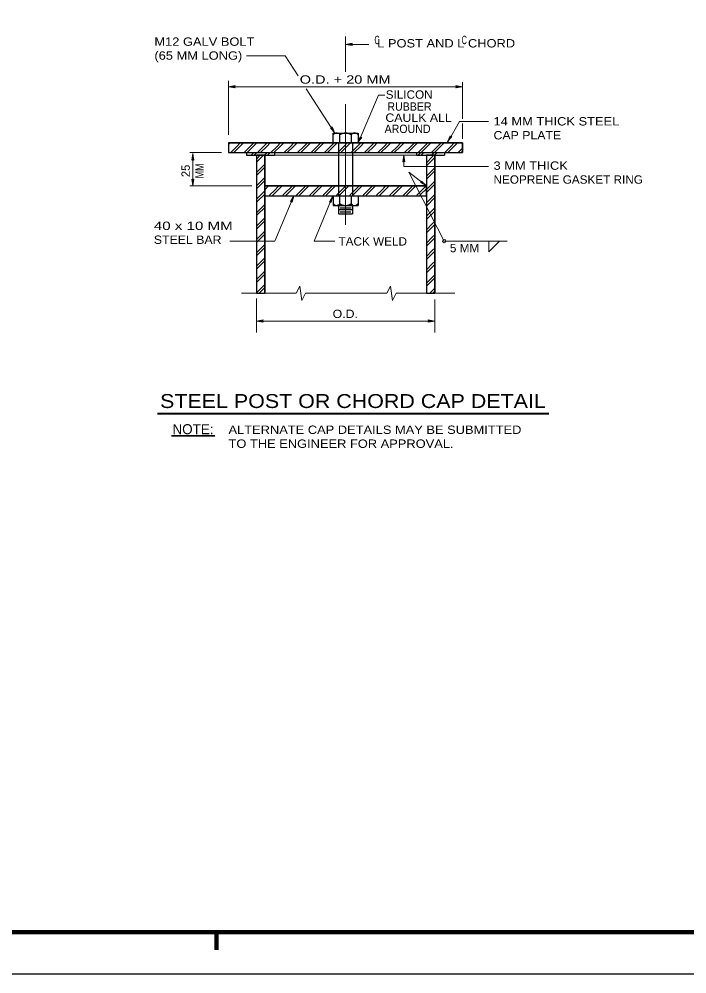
# Model space of a CAD drawing. Extents: x 312601.859 to 312602.7, y 144420.109 to 144420.704.
# Drawn here: x 312602.209 to 312602.4486, y 144420.1095 to 144420.4522 of the extents above; entities that cross this region are included whole.
import ezdxf
from ezdxf.enums import TextEntityAlignment as Align

# ---------------------------------------------------------------- set-up
doc = ezdxf.new("R2010")
doc.units = 0
doc.header["$LTSCALE"] = 0.0012
doc.linetypes.add('DOT_DASHED', pattern=[7.7, 5, -1.2, 0.3, -1.2])
doc.linetypes.add('MEDIUM_DASHED', pattern=[4.5, 3, -1.5])
for name, color, linetype, lineweight in [('1', 7, 'Continuous', 13), ('2', 7, 'Continuous', 13), ('39', 7, 'Continuous', 13)]:
    doc.layers.add(name, color=color, linetype=linetype, lineweight=lineweight)

msp = doc.modelspace()

# ---------------------------------------------------------------- hatches: boundary and pattern name
at = {"layer": '39'}
for points in [[(312602.3283, 144420.4431), (312602.3285, 144420.4427), (312602.3261, 144420.4431), (312602.3285, 144420.4435)], [(312602.2863, 144420.4279), (312602.2865, 144420.4275), (312602.2841, 144420.4279), (312602.2865, 144420.4283)], [(312602.3659, 144420.4279), (312602.3657, 144420.4283), (312602.3681, 144420.4279), (312602.3657, 144420.4275)], [(312602.3211, 144420.4131), (312602.3213, 144420.4135), (312602.3223, 144420.4113), (312602.3207, 144420.4131)], [(312602.3315, 144420.4097), (312602.3319, 144420.4097), (312602.3304, 144420.4078), (312602.3313, 144420.4099)], [(312602.3638, 144420.41), (312602.3642, 144420.41), (312602.3627, 144420.4081), (312602.3636, 144420.4103)], [(312602.2713, 144420.4018), (312602.2709, 144420.4016), (312602.2713, 144420.404), (312602.2717, 144420.4016)], [(312602.347, 144420.4011), (312602.3466, 144420.4009), (312602.347, 144420.4033), (312602.3474, 144420.4009)], [(312602.2713, 144420.3945), (312602.2717, 144420.3947), (312602.2713, 144420.3923), (312602.2709, 144420.3947)], [(312602.3534, 144420.3936), (312602.3534, 144420.394), (312602.3551, 144420.3923), (312602.353, 144420.3935)], [(312602.3067, 144420.3868), (312602.3063, 144420.3867), (312602.3075, 144420.3888), (312602.3069, 144420.3865)], [(312602.3207, 144420.3867), (312602.3203, 144420.3866), (312602.3215, 144420.3887), (312602.3209, 144420.3864)], [(312602.2963, 144420.3438), (312602.2965, 144420.3434), (312602.2941, 144420.3438), (312602.2965, 144420.3442)], [(312602.3559, 144420.3438), (312602.3557, 144420.3442), (312602.3581, 144420.3438), (312602.3557, 144420.3434)]]:
    msp.add_hatch(color=256, dxfattribs=at).paths.add_polyline_path(points)

# ---------------------------------------------------------------- linework, layer by layer
at = {"layer": '1', "lineweight": 40}
msp.add_line((312602.2586, 144420.3106), (312602.399, 144420.3106), dxfattribs=at)
at = {"layer": '2'}
for p, q in [((312602.3261, 144420.4459), (312602.3261, 144420.4332)), ((312602.3261, 144420.4431), (312602.3344, 144420.4431)), ((312602.2906, 144420.439), (312602.3044, 144420.439)), ((312602.3091, 144420.4318), (312602.3044, 144420.439)), ((312602.2841, 144420.43), (312602.2841, 144420.4107)), ((312602.3681, 144420.4296), (312602.3681, 144420.4164)), ((312602.2841, 144420.4279), (312602.3681, 144420.4279)), ((312602.3223, 144420.4113), (312602.312, 144420.4272)), ((312602.3628, 144420.408), (312602.367, 144420.4154)), ((312602.367, 144420.4154), (312602.3774, 144420.4154)), ((312602.3681, 144420.4147), (312602.3681, 144420.4092)), ((312602.3216, 144420.4107), (312602.3216, 144420.4113)), ((312602.2841, 144420.4072), (312602.2847, 144420.4078)), ((312602.2849, 144420.4043), (312602.2871, 144420.4065)), ((312602.286, 144420.4043), (312602.2882, 144420.4065)), ((312602.2871, 144420.4065), (312602.2882, 144420.4076)), ((312602.2882, 144420.4065), (312602.2895, 144420.4078)), ((312602.2882, 144420.4076), (312602.2884, 144420.4078)), ((312602.2897, 144420.4043), (312602.2919, 144420.4065)), ((312602.2908, 144420.4043), (312602.293, 144420.4065)), ((312602.2919, 144420.4065), (312602.2932, 144420.4078)), ((312602.293, 144420.4065), (312602.2943, 144420.4078)), ((312602.2945, 144420.4043), (312602.2967, 144420.4065)), ((312602.2956, 144420.4043), (312602.2978, 144420.4065)), ((312602.2967, 144420.4065), (312602.298, 144420.4078)), ((312602.2978, 144420.4065), (312602.2991, 144420.4078)), ((312602.2993, 144420.4043), (312602.3015, 144420.4065)), ((312602.3004, 144420.4043), (312602.3026, 144420.4065)), ((312602.3015, 144420.4065), (312602.3028, 144420.4078)), ((312602.3026, 144420.4065), (312602.3039, 144420.4078)), ((312602.3041, 144420.4043), (312602.3063, 144420.4065)), ((312602.3052, 144420.4043), (312602.3074, 144420.4065)), ((312602.3063, 144420.4065), (312602.3074, 144420.4076)), ((312602.3074, 144420.4065), (312602.3087, 144420.4078)), ((312602.3074, 144420.4076), (312602.3076, 144420.4078)), ((312602.3089, 144420.4043), (312602.3111, 144420.4065)), ((312602.31, 144420.4043), (312602.3122, 144420.4065)), ((312602.3111, 144420.4065), (312602.3124, 144420.4078)), ((312602.3122, 144420.4065), (312602.3135, 144420.4078)), ((312602.3137, 144420.4043), (312602.3159, 144420.4065)), ((312602.3148, 144420.4043), (312602.317, 144420.4065)), ((312602.3159, 144420.4065), (312602.3172, 144420.4078)), ((312602.317, 144420.4065), (312602.3183, 144420.4078)), ((312602.3185, 144420.4043), (312602.3207, 144420.4065)), ((312602.3196, 144420.4043), (312602.3218, 144420.4065)), ((312602.3207, 144420.4065), (312602.322, 144420.4078)), ((312602.3218, 144420.4065), (312602.3231, 144420.4078)), ((312602.3233, 144420.4043), (312602.3255, 144420.4065)), ((312602.3244, 144420.4043), (312602.3266, 144420.4065)), ((312602.3255, 144420.4065), (312602.3266, 144420.4076)), ((312602.3266, 144420.4065), (312602.3279, 144420.4078)), ((312602.3266, 144420.4076), (312602.3268, 144420.4078)), ((312602.3281, 144420.4043), (312602.3303, 144420.4065)), ((312602.3292, 144420.4043), (312602.3314, 144420.4065)), ((312602.3303, 144420.4065), (312602.3316, 144420.4078)), ((312602.3314, 144420.4065), (312602.3327, 144420.4078)), ((312602.3329, 144420.4043), (312602.3351, 144420.4065)), ((312602.334, 144420.4043), (312602.3362, 144420.4065)), ((312602.3351, 144420.4065), (312602.3364, 144420.4078)), ((312602.3362, 144420.4065), (312602.3375, 144420.4078)), ((312602.3377, 144420.4043), (312602.3399, 144420.4065)), ((312602.3388, 144420.4043), (312602.341, 144420.4065)), ((312602.3399, 144420.4065), (312602.3412, 144420.4078)), ((312602.341, 144420.4065), (312602.3423, 144420.4078)), ((312602.3425, 144420.4043), (312602.3447, 144420.4065)), ((312602.3436, 144420.4043), (312602.3458, 144420.4065)), ((312602.3447, 144420.4065), (312602.3458, 144420.4076)), ((312602.3458, 144420.4065), (312602.3471, 144420.4078)), ((312602.3458, 144420.4076), (312602.346, 144420.4078)), ((312602.3473, 144420.4043), (312602.3495, 144420.4065)), ((312602.3484, 144420.4043), (312602.3506, 144420.4065)), ((312602.3495, 144420.4065), (312602.3508, 144420.4078)), ((312602.3506, 144420.4065), (312602.3519, 144420.4078)), ((312602.3521, 144420.4043), (312602.3543, 144420.4065)), ((312602.3532, 144420.4043), (312602.3554, 144420.4065)), ((312602.3543, 144420.4065), (312602.3556, 144420.4078)), ((312602.3554, 144420.4065), (312602.3567, 144420.4078)), ((312602.3569, 144420.4043), (312602.3591, 144420.4065)), ((312602.358, 144420.4043), (312602.3602, 144420.4065)), ((312602.3591, 144420.4065), (312602.3604, 144420.4078)), ((312602.3602, 144420.4065), (312602.3615, 144420.4078)), ((312602.3617, 144420.4043), (312602.3639, 144420.4065)), ((312602.3628, 144420.4043), (312602.365, 144420.4065)), ((312602.3639, 144420.4065), (312602.365, 144420.4076)), ((312602.365, 144420.4065), (312602.3663, 144420.4078)), ((312602.365, 144420.4076), (312602.3652, 144420.4078)), ((312602.3665, 144420.4043), (312602.3681, 144420.4059)), ((312602.3676, 144420.4043), (312602.3681, 144420.4048)), ((312602.2702, 144420.4043), (312602.2816, 144420.4043)), ((312602.2713, 144420.404), (312602.2713, 144420.3923)), ((312602.2922, 144420.4033), (312602.2932, 144420.4043)), ((312602.2933, 144420.4033), (312602.2943, 144420.4043)), ((312602.2941, 144420.4019), (312602.2955, 144420.4033)), ((312602.2941, 144420.4008), (312602.2945, 144420.4012)), ((312602.2945, 144420.4012), (312602.2966, 144420.4033)), ((312602.297, 144420.4033), (312602.298, 144420.4043)), ((312602.2981, 144420.4033), (312602.2991, 144420.4043)), ((312602.3006, 144420.4033), (312602.3516, 144420.4033)), ((312602.347, 144420.3993), (312602.347, 144420.4033)), ((312602.3532, 144420.4033), (312602.3536, 144420.4037)), ((312602.3536, 144420.4037), (312602.3542, 144420.4043)), ((312602.3551, 144420.4006), (312602.3572, 144420.4027)), ((312602.3551, 144420.3995), (312602.3581, 144420.4025)), ((312602.3569, 144420.4033), (312602.3573, 144420.4037)), ((312602.3572, 144420.4027), (312602.3578, 144420.4033)), ((312602.3573, 144420.4037), (312602.3579, 144420.4043)), ((312602.358, 144420.4033), (312602.3584, 144420.4037)), ((312602.3584, 144420.4037), (312602.359, 144420.4043)), ((312602.2941, 144420.3971), (312602.2971, 144420.4001)), ((312602.2945, 144420.3964), (312602.2971, 144420.399)), ((312602.347, 144420.3993), (312602.3774, 144420.3993)), ((312602.3551, 144420.3958), (312602.3572, 144420.3979)), ((312602.3551, 144420.3947), (312602.3581, 144420.3977)), ((312602.3572, 144420.3979), (312602.3581, 144420.3988)), ((312602.2941, 144420.396), (312602.2945, 144420.3964)), ((312602.2941, 144420.3923), (312602.2971, 144420.3953)), ((312602.2945, 144420.3916), (312602.2971, 144420.3942)), ((312602.2702, 144420.3923), (312602.2925, 144420.3923)), ((312602.2941, 144420.3912), (312602.2945, 144420.3916)), ((312602.2971, 144420.3909), (312602.2985, 144420.3923)), ((312602.2971, 144420.392), (312602.2974, 144420.3923)), ((312602.3003, 144420.3893), (312602.3033, 144420.3923)), ((312602.3003, 144420.3904), (312602.3022, 144420.3923)), ((312602.304, 144420.3893), (312602.307, 144420.3923)), ((312602.3051, 144420.3893), (312602.3081, 144420.3923)), ((312602.3088, 144420.3893), (312602.3118, 144420.3923)), ((312602.3099, 144420.3893), (312602.3129, 144420.3923)), ((312602.3136, 144420.3893), (312602.3166, 144420.3923)), ((312602.3147, 144420.3893), (312602.3177, 144420.3923)), ((312602.3195, 144420.3893), (312602.3225, 144420.3923)), ((312602.3195, 144420.3904), (312602.3214, 144420.3923)), ((312602.3232, 144420.3893), (312602.3262, 144420.3923)), ((312602.3243, 144420.3893), (312602.3273, 144420.3923)), ((312602.328, 144420.3893), (312602.331, 144420.3923)), ((312602.3291, 144420.3893), (312602.3321, 144420.3923)), ((312602.3328, 144420.3893), (312602.3358, 144420.3923)), ((312602.3339, 144420.3893), (312602.3369, 144420.3923)), ((312602.3387, 144420.3893), (312602.3417, 144420.3923)), ((312602.3387, 144420.3904), (312602.3406, 144420.3923)), ((312602.3424, 144420.3893), (312602.3454, 144420.3923)), ((312602.3435, 144420.3893), (312602.3465, 144420.3923)), ((312602.3472, 144420.3893), (312602.3502, 144420.3923)), ((312602.3483, 144420.3893), (312602.3513, 144420.3923)), ((312602.3551, 144420.3923), (312602.3487, 144420.3923)), ((312602.352, 144420.3893), (312602.355, 144420.3923)), ((312602.3531, 144420.3893), (312602.3551, 144420.3913)), ((312602.3551, 144420.391), (312602.3572, 144420.3931)), ((312602.3551, 144420.3899), (312602.3581, 144420.3929)), ((312602.3572, 144420.3931), (312602.3581, 144420.394)), ((312602.2941, 144420.3875), (312602.2971, 144420.3905)), ((312602.2945, 144420.3868), (312602.2971, 144420.3894)), ((312602.2987, 144420.3888), (312602.2992, 144420.3893)), ((312602.2992, 144420.3893), (312602.3003, 144420.3904)), ((312602.2998, 144420.3888), (312602.3003, 144420.3893)), ((312602.3035, 144420.3888), (312602.304, 144420.3893)), ((312602.3046, 144420.3888), (312602.3051, 144420.3893)), ((312602.3083, 144420.3888), (312602.3088, 144420.3893)), ((312602.3094, 144420.3888), (312602.3099, 144420.3893)), ((312602.3131, 144420.3888), (312602.3136, 144420.3893)), ((312602.3142, 144420.3888), (312602.3147, 144420.3893)), ((312602.3215, 144420.3887), (312602.3148, 144420.3725)), ((312602.3179, 144420.3888), (312602.3184, 144420.3893)), ((312602.3184, 144420.3893), (312602.3195, 144420.3904)), ((312602.319, 144420.3888), (312602.3195, 144420.3893)), ((312602.3227, 144420.3888), (312602.3232, 144420.3893)), ((312602.3238, 144420.3888), (312602.3243, 144420.3893)), ((312602.3275, 144420.3888), (312602.328, 144420.3893)), ((312602.3286, 144420.3888), (312602.3291, 144420.3893)), ((312602.3323, 144420.3888), (312602.3328, 144420.3893)), ((312602.3334, 144420.3888), (312602.3339, 144420.3893)), ((312602.3371, 144420.3888), (312602.3376, 144420.3893)), ((312602.3376, 144420.3893), (312602.3387, 144420.3904)), ((312602.3382, 144420.3888), (312602.3387, 144420.3893)), ((312602.3419, 144420.3888), (312602.3424, 144420.3893)), ((312602.343, 144420.3888), (312602.3435, 144420.3893)), ((312602.3467, 144420.3888), (312602.3472, 144420.3893)), ((312602.3478, 144420.3888), (312602.3483, 144420.3893)), ((312602.3515, 144420.3888), (312602.352, 144420.3893)), ((312602.3526, 144420.3888), (312602.3531, 144420.3893)), ((312602.3551, 144420.3862), (312602.3572, 144420.3883)), ((312602.3551, 144420.3851), (312602.3581, 144420.3881)), ((312602.3572, 144420.3883), (312602.3581, 144420.3892)), ((312602.2941, 144420.3864), (312602.2945, 144420.3868)), ((312602.2941, 144420.3827), (312602.2971, 144420.3857)), ((312602.2945, 144420.382), (312602.2971, 144420.3846)), ((312602.3572, 144420.3835), (312602.3581, 144420.3844)), ((312602.2941, 144420.3816), (312602.2945, 144420.382)), ((312602.2941, 144420.3779), (312602.2971, 144420.3809)), ((312602.3551, 144420.3814), (312602.3572, 144420.3835)), ((312602.3551, 144420.3803), (312602.3581, 144420.3833)), ((312602.2941, 144420.3768), (312602.2945, 144420.3772)), ((312602.2945, 144420.3772), (312602.2971, 144420.3798)), ((312602.3551, 144420.3766), (312602.3572, 144420.3787)), ((312602.3551, 144420.3755), (312602.3581, 144420.3785)), ((312602.3572, 144420.3787), (312602.3581, 144420.3796)), ((312602.2941, 144420.3731), (312602.2971, 144420.3761)), ((312602.2945, 144420.3724), (312602.2971, 144420.375)), ((312602.3551, 144420.3718), (312602.3572, 144420.3739)), ((312602.3551, 144420.3707), (312602.3581, 144420.3737)), ((312602.3572, 144420.3739), (312602.3581, 144420.3748)), ((312602.2941, 144420.372), (312602.2945, 144420.3724)), ((312602.2941, 144420.3683), (312602.2971, 144420.3713)), ((312602.2945, 144420.3676), (312602.2971, 144420.3702)), ((312602.3223, 144420.3725), (312602.3148, 144420.3725)), ((312602.3841, 144420.3725), (312602.3615, 144420.3725)), ((312602.2941, 144420.3672), (312602.2945, 144420.3676)), ((312602.3551, 144420.367), (312602.3572, 144420.3691)), ((312602.3551, 144420.3659), (312602.3581, 144420.3689)), ((312602.3572, 144420.3691), (312602.3581, 144420.37)), ((312602.2941, 144420.3635), (312602.2971, 144420.3665)), ((312602.2945, 144420.3628), (312602.2971, 144420.3654)), ((312602.3551, 144420.3622), (312602.3572, 144420.3643)), ((312602.3551, 144420.3611), (312602.3581, 144420.3641)), ((312602.3572, 144420.3643), (312602.3581, 144420.3652)), ((312602.2941, 144420.3624), (312602.2945, 144420.3628)), ((312602.2941, 144420.3587), (312602.2971, 144420.3617)), ((312602.2945, 144420.358), (312602.2971, 144420.3606)), ((312602.3572, 144420.3595), (312602.3581, 144420.3604)), ((312602.2941, 144420.3576), (312602.2945, 144420.358)), ((312602.2941, 144420.3539), (312602.2971, 144420.3569)), ((312602.3551, 144420.3574), (312602.3572, 144420.3595)), ((312602.3551, 144420.3563), (312602.3581, 144420.3593)), ((312602.2887, 144420.3538), (312602.3084, 144420.3538)), ((312602.2951, 144420.3538), (312602.2971, 144420.3558)), ((312602.3117, 144420.3538), (312602.3409, 144420.3538)), ((312602.3442, 144420.3538), (312602.3653, 144420.3538)), ((312602.3563, 144420.3538), (312602.3572, 144420.3547)), ((312602.3572, 144420.3547), (312602.3581, 144420.3556)), ((312602.3574, 144420.3538), (312602.3581, 144420.3545)), ((312602.2941, 144420.3519), (312602.2941, 144420.3397)), ((312602.3581, 144420.3515), (312602.3581, 144420.3397)), ((312602.2941, 144420.3438), (312602.3581, 144420.3438))]:
    msp.add_line(p, q, dxfattribs=at)
at = {"layer": '2', "linetype": 'DOT_DASHED'}
msp.add_line((312602.3261, 144420.4217), (312602.3261, 144420.3784), dxfattribs=at)
at = {"layer": '2', "lineweight": 25}
for p, q in [((312602.3241, 144420.4078), (312602.3241, 144420.4113)), ((312602.3281, 144420.4113), (312602.3281, 144420.4078)), ((312602.3306, 144420.4113), (312602.3306, 144420.4078)), ((312602.2841, 144420.4078), (312602.3681, 144420.4078)), ((312602.2841, 144420.4078), (312602.2841, 144420.4043)), ((312602.3681, 144420.4078), (312602.3681, 144420.4043)), ((312602.2841, 144420.4043), (312602.3681, 144420.4043)), ((312602.2841, 144420.4043), (312602.3132, 144420.4043)), ((312602.2906, 144420.4043), (312602.2906, 144420.4033)), ((312602.2906, 144420.4033), (312602.3006, 144420.4033)), ((312602.2941, 144420.4033), (312602.2941, 144420.3538)), ((312602.2971, 144420.4033), (312602.2971, 144420.3538)), ((312602.3006, 144420.4043), (312602.3006, 144420.4033)), ((312602.3236, 144420.4043), (312602.3236, 144420.3923)), ((312602.3286, 144420.4043), (312602.3286, 144420.3923)), ((312602.3516, 144420.4043), (312602.3516, 144420.4033)), ((312602.3516, 144420.4033), (312602.3616, 144420.4033)), ((312602.3551, 144420.4033), (312602.3551, 144420.3538)), ((312602.3581, 144420.4033), (312602.3581, 144420.3538)), ((312602.3616, 144420.4043), (312602.3616, 144420.4033)), ((312602.2971, 144420.3923), (312602.3551, 144420.3923)), ((312602.2971, 144420.3888), (312602.3551, 144420.3888)), ((312602.3241, 144420.3853), (312602.3241, 144420.3888)), ((312602.3281, 144420.3888), (312602.3281, 144420.3853)), ((312602.3306, 144420.3888), (312602.3306, 144420.3853)), ((312602.3236, 144420.3853), (312602.3236, 144420.3823)), ((312602.3242, 144420.3845), (312602.3281, 144420.3845)), ((312602.3286, 144420.3853), (312602.3286, 144420.3823)), ((312602.3236, 144420.3838), (312602.3286, 144420.3838)), ((312602.3236, 144420.3823), (312602.3286, 144420.3823)), ((312602.3242, 144420.383), (312602.328, 144420.383))]:
    msp.add_line(p, q, dxfattribs=at)
at = {"layer": '2', "linetype": 'MEDIUM_DASHED', "lineweight": 25}
for p, q in [((312602.3236, 144420.4078), (312602.3236, 144420.4043)), ((312602.3286, 144420.4078), (312602.3286, 144420.4043)), ((312602.3236, 144420.3923), (312602.3236, 144420.3888)), ((312602.3286, 144420.3923), (312602.3286, 144420.3888))]:
    msp.add_line(p, q, dxfattribs=at)
at = {"layer": '2', "lineweight": 35}
msp.add_line((312602.2792, 144420.3026), (312602.2636, 144420.3026), dxfattribs=at)
at = {"layer": '2'}
for points in [[(312602.3306, 144420.4078), (312602.3379, 144420.4249), (312602.3402, 144420.4249)], [(312602.3521, 144420.4033), (312602.3525, 144420.4037), (312602.3531, 144420.4043)], [(312602.3551, 144420.3923), (312602.3488, 144420.3972), (312602.3615, 144420.3725)], [(312602.3075, 144420.3888), (312602.3007, 144420.3725), (312602.2846, 144420.3725)], [(312602.3775, 144420.3725), (312602.3775, 144420.3687), (312602.3813, 144420.3725)], [(312602.3084, 144420.3538), (312602.3097, 144420.3563), (312602.3104, 144420.3512), (312602.3117, 144420.3538)], [(312602.3409, 144420.3538), (312602.3422, 144420.3563), (312602.3429, 144420.3512), (312602.3442, 144420.3538)]]:
    msp.add_lwpolyline(points, dxfattribs=at)
at = {"layer": '2', "lineweight": 25}
for points in [[(312602.3216, 144420.4078), (312602.3216, 144420.4113), (312602.3306, 144420.4113)], [(312602.3132, 144420.4043), (312602.3681, 144420.4043), (312602.3681, 144420.4078), (312602.2841, 144420.4078)], [(312602.3216, 144420.3888), (312602.3216, 144420.3853), (312602.3306, 144420.3853)]]:
    msp.add_lwpolyline(points, dxfattribs=at)
for points in [[(312602.2941, 144420.3783), (312602.2941, 144420.3538), (312602.2971, 144420.3538), (312602.2971, 144420.4033), (312602.2941, 144420.4033)], [(312602.3551, 144420.3797), (312602.3551, 144420.3538), (312602.3581, 144420.3538), (312602.3581, 144420.4033), (312602.3551, 144420.4033)], [(312602.3125, 144420.3888), (312602.3551, 144420.3888), (312602.3551, 144420.3923), (312602.2971, 144420.3923), (312602.2971, 144420.3888)]]:
    msp.add_lwpolyline(points, close=True, dxfattribs=at)
at = {"layer": '2'}
msp.add_circle((312602.3615, 144420.3725), 0.0006083, dxfattribs=at)
at = {"layer": '2', "lineweight": 25}
for centre, radius, start, end in [((312602.32935, 144420.40985), 0.0014577, 30.96376, 149.03624), ((312602.32285, 144420.409836), 0.0014651, 31.44281, 148.55719), ((312602.3261, 144420.408093), 0.0032071, 51.41991, 128.58009), ((312602.32285, 144420.386764), 0.0014651, 211.44281, 328.55719), ((312602.3261, 144420.388507), 0.0032071, 231.41991, 308.58009), ((312602.32935, 144420.38675), 0.0014577, 210.96376, 329.03624)]:
    msp.add_arc(centre, radius, start, end, dxfattribs=at)
at = {"layer": '39', "lineweight": 158}
msp.add_line((312602.2798, 144420.1181), (312602.2798, 144420.1245), dxfattribs=at)
at = {"layer": '39', "lineweight": 25}
msp.add_lwpolyline([(312601.8593, 144420.1095), (312602.7003, 144420.1095), (312602.7003, 144420.7035)], dxfattribs=at)
at = {"layer": '39', "lineweight": 158}
msp.add_lwpolyline([(312601.9103, 144420.1245), (312602.6853, 144420.1245), (312602.6853, 144420.6645)], dxfattribs=at)
at = {"layer": '39'}
for points in [[(312602.3283, 144420.4431), (312602.3285, 144420.4427), (312602.3261, 144420.4431), (312602.3285, 144420.4435)], [(312602.2863, 144420.4279), (312602.2865, 144420.4275), (312602.2841, 144420.4279), (312602.2865, 144420.4283)], [(312602.3659, 144420.4279), (312602.3657, 144420.4283), (312602.3681, 144420.4279), (312602.3657, 144420.4275)], [(312602.3211, 144420.4131), (312602.3213, 144420.4135), (312602.3223, 144420.4113), (312602.3207, 144420.4131)], [(312602.3315, 144420.4097), (312602.3319, 144420.4097), (312602.3304, 144420.4078), (312602.3313, 144420.4099)], [(312602.3638, 144420.41), (312602.3642, 144420.41), (312602.3627, 144420.4081), (312602.3636, 144420.4103)], [(312602.2713, 144420.4018), (312602.2709, 144420.4016), (312602.2713, 144420.404), (312602.2717, 144420.4016)], [(312602.347, 144420.4011), (312602.3466, 144420.4009), (312602.347, 144420.4033), (312602.3474, 144420.4009)], [(312602.2713, 144420.3945), (312602.2717, 144420.3947), (312602.2713, 144420.3923), (312602.2709, 144420.3947)], [(312602.3534, 144420.3936), (312602.3534, 144420.394), (312602.3551, 144420.3923), (312602.353, 144420.3935)], [(312602.3067, 144420.3868), (312602.3063, 144420.3867), (312602.3075, 144420.3888), (312602.3069, 144420.3865)], [(312602.3207, 144420.3867), (312602.3203, 144420.3866), (312602.3215, 144420.3887), (312602.3209, 144420.3864)], [(312602.2963, 144420.3438), (312602.2965, 144420.3434), (312602.2941, 144420.3438), (312602.2965, 144420.3442)], [(312602.3559, 144420.3438), (312602.3557, 144420.3442), (312602.3581, 144420.3438), (312602.3557, 144420.3434)]]:
    msp.add_lwpolyline(points, close=True, dxfattribs=at)

# ---------------------------------------------------------------- texts
at = {"layer": '2'}
for s, width, p in [('M12 GALV BOLT', 1.15, (312602.2575, 144420.4426)), ('(65 MM LONG)', 1.15, (312602.2575, 144420.4376)), ('SILICON', 1.05, (312602.3405, 144420.4236)), ('RUBBER', 0.95, (312602.3411, 144420.4193)), ('CAULK ALL', 1.1, (312602.3404, 144420.4153)), ('14 MM THICK STEEL', 1.15, (312602.3792, 144420.414)), ('AROUND', 0.95, (312602.3401, 144420.4113)), ('CAP PLATE', 1.1, (312602.3792, 144420.409)), ('3 MM THICK', 1.15, (312602.3792, 144420.3981)), ('NEOPRENE GASKET RING', 1.05, (312602.3792, 144420.3931)), ('40 x 10 MM', 1.35, (312602.2573, 144420.3765)), ('STEEL BAR', 1.1, (312602.2573, 144420.3715)), ('ALTERNATE CAP DETAILS MAY BE SUBMITTED', 1.15, (312602.2841, 144420.3033)), ('TO THE ENGINEER FOR APPROVAL.', 1.15, (312602.2841, 144420.2983))]:
    msp.add_text(s, height=0.003, dxfattribs=dict(at, width=width)).set_placement(p)
for s, height, width, p in [('C', 0.003, 0.6, (312602.3374, 144420.4432)), ('C', 0.003, 0.6, (312602.3687, 144420.4432)), ('L POST AND L CHORD', 0.003, 1.15, (312602.3622, 144420.442)), ('O.D. + 20 MM', 0.003, 1.3, (312602.32595, 144420.429)), ('TACK WELD', 0.003, 1.05, (312602.33585, 144420.3709)), ('5 MM', 0.003, 1.05, (312602.3688, 144420.3685)), ('O.D.', 0.003, 1.1, (312602.326, 144420.3449)), ('STEEL POST OR CHORD CAP DETAIL', 0.005, 1.15, (312602.32875, 144420.3126))]:
    msp.add_text(s, height=height, dxfattribs=dict(at, width=width)).set_placement(p, align=Align.CENTER)
msp.add_text('25', height=0.003, rotation=90, dxfattribs=at).set_placement((312602.2702, 144420.3977), align=Align.CENTER)
at = {"layer": '2', "width": 0.8}
msp.add_text('MM', height=0.003, rotation=90, dxfattribs=at).set_placement((312602.2752, 144420.3977), align=Align.CENTER)
at = {"layer": '2'}
msp.add_text('NOTE:', height=0.0036, dxfattribs=at).set_placement((312602.27135, 144420.3032), align=Align.CENTER)

doc.saveas('drawing.dxf')
